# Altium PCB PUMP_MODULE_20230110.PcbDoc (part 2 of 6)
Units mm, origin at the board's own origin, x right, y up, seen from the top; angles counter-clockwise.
Board outline 260.15 x 142.01 mm, 4 copper layers (Top Layer, Mid-Layer 1, Mid-Layer 2, Bottom Layer); 422 components, 240 nets, 1746 pads, 416 vias.
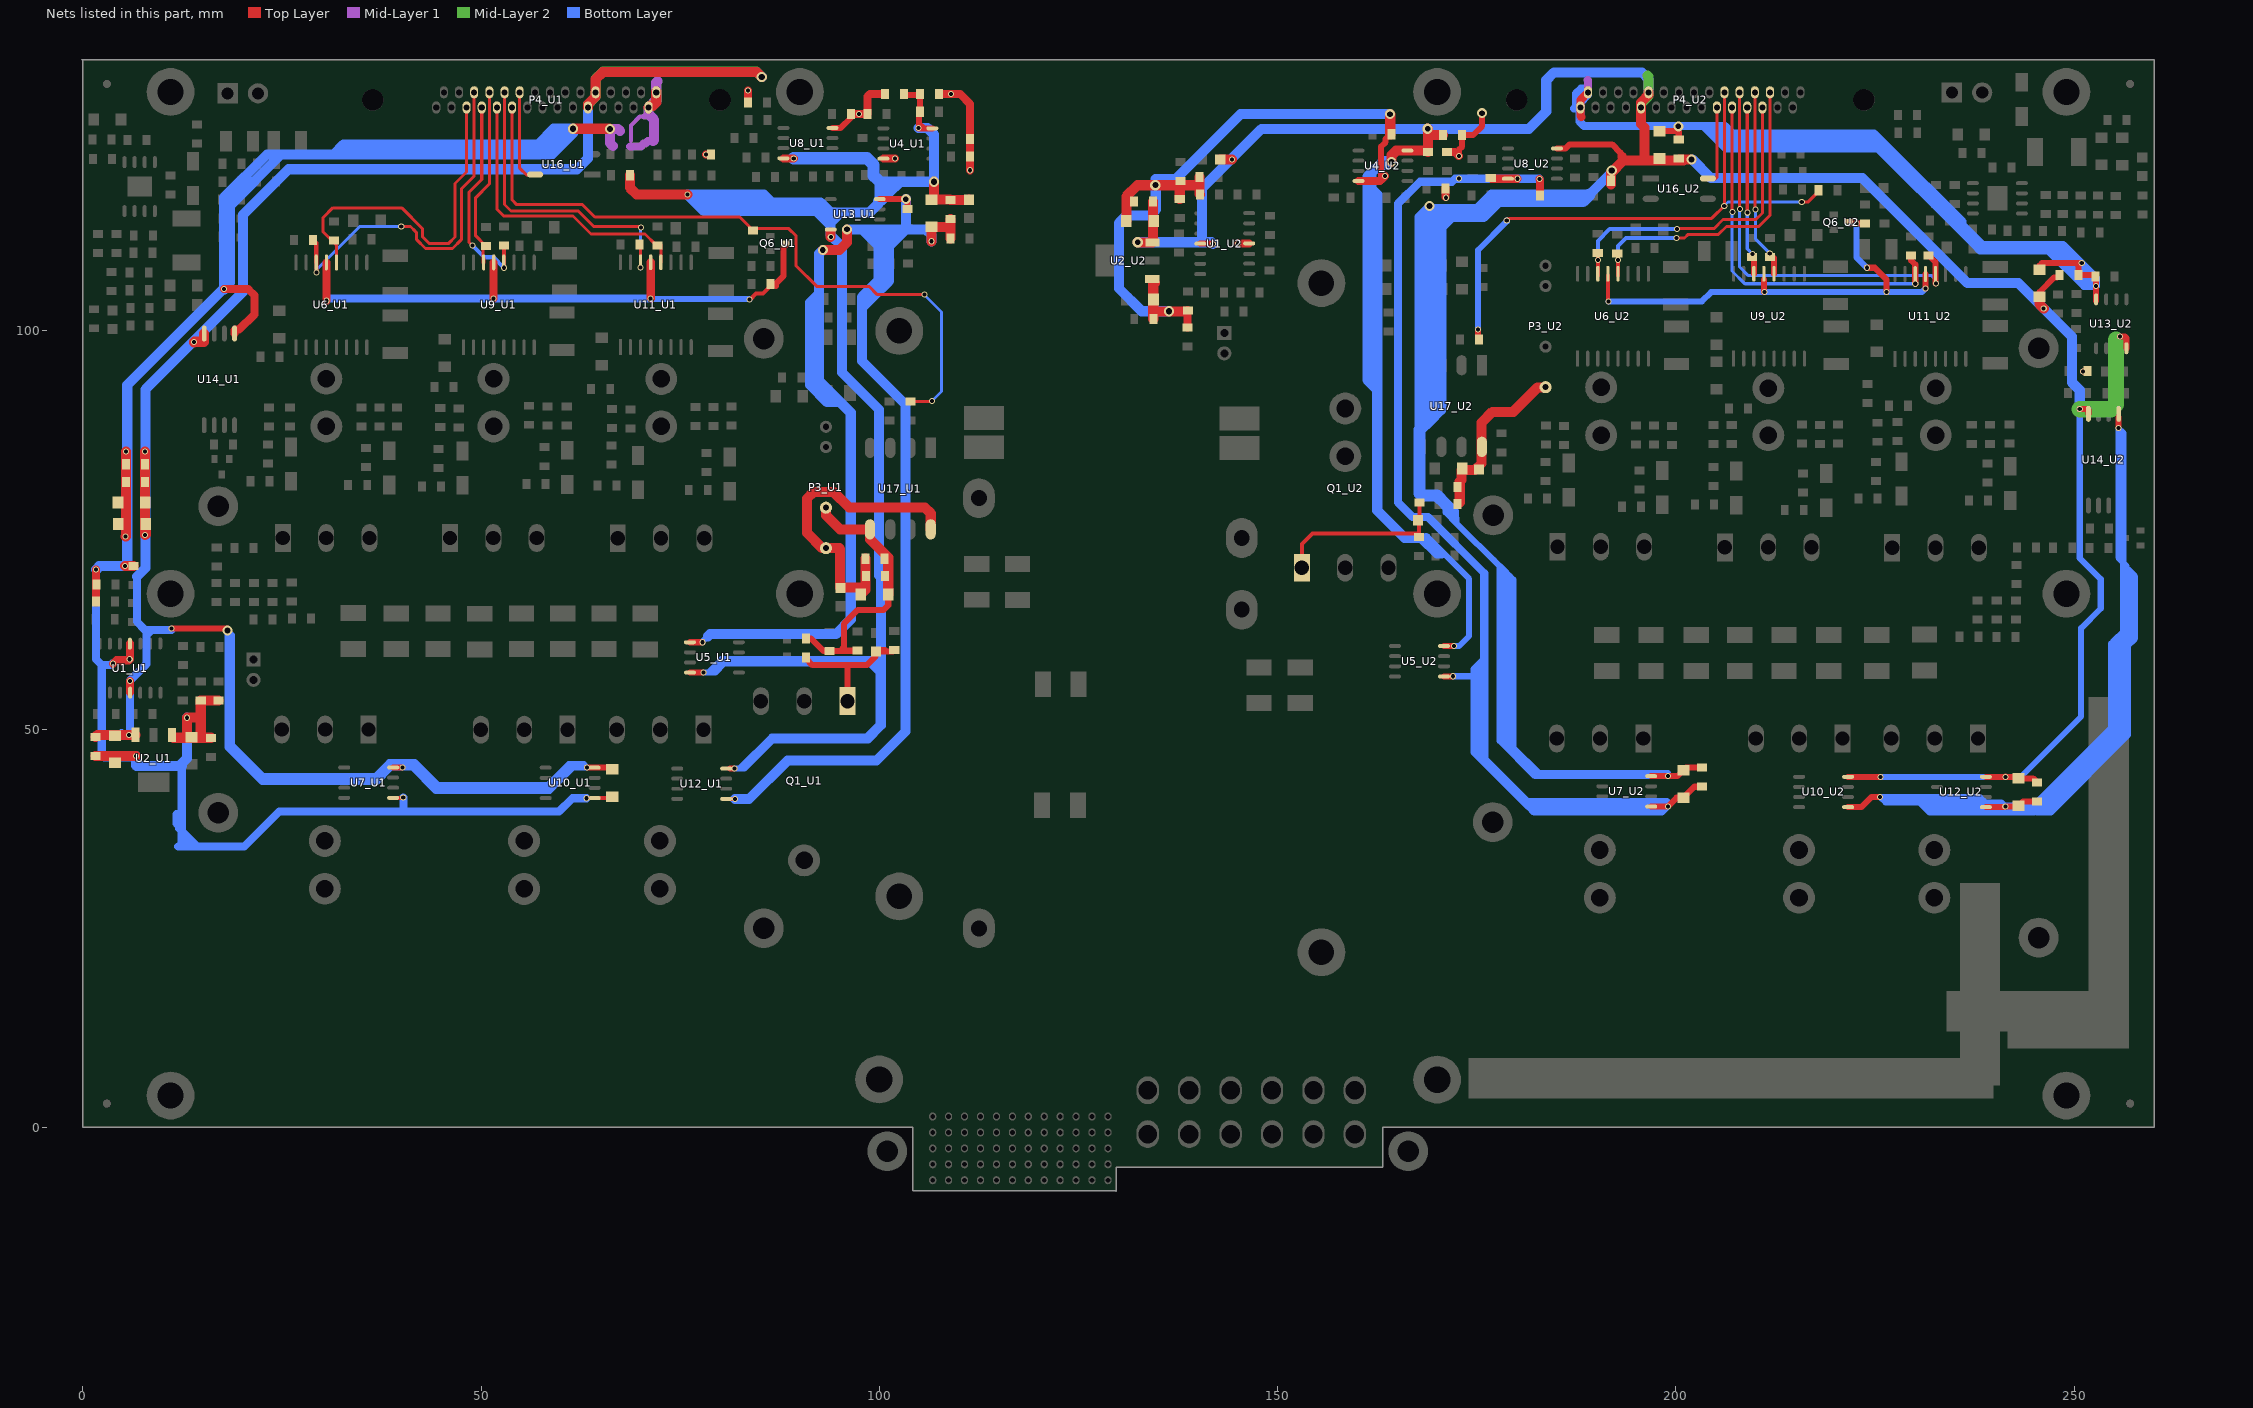
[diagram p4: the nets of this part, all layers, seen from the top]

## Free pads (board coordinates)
  rect 2.54x2.54 on Top Solder: 0(30.302,69.52) 0(51.587,69.596) 0(72.466,69.723) ""(161.417,9.855)
  rect 4.572x5.08 on Bottom Solder: 1(153.619,63.475) 1(190.221,54.534) 11(30.734,60.63) 11(30.759,55.448)
  rect 5.08x10.16 on Bottom Solder: 1(191.745,60.528) 1(195.301,64.186) 6(204.14,24.384) 6(204.14,33.35) 6(204.14,43.104) 7(243.713,85.573) 7(243.713,87.63)
  rect 5.08x8.89 on Bottom Solder: 1(224.714,58.268) 1(224.714,63.627) 1(234.315,58.42) 1(234.315,61.316) 1(236.957,63.957)
  rect 5.08x11.43 on Bottom Solder: 2(203.733,60.604) 2(204.14,53.467) 2(204.14,60.604) 2(213.411,60.274) 2(216.306,63.602)
  rect 5.08x3.81 on Bottom Solder: 3(232.664,54.077) 12(83.642,36.754) 12(91.999,40.869) 12(93.396,40.869) 12(98.273,40.869)
  rect 2.54x2.032 on Bottom Solder rot 135: 4(41.478,80.239) 4(41.656,80.797) 4(62.459,81.382) 4(201.016,79.832) 4(222.301,78.892) 4(224.231,68.224)
  rect 5.08x2.54 on Bottom Solder rot 45: 4(42.088,33.071)
  rect 5.08x3.81 on Bottom Solder rot 45: 4(191.11,57.455) 4(191.643,55.55) 4(192.329,66.091) 4(194.716,58.623) 4(214.071,66.091)
  rect 2.54x3.81 on Bottom Solder rot 135: 4(201.371,36.601) 4(216.56,54.254)
  rect 2.54x3.81 on Bottom Solder rot 45: 4(203.632,66.726) 4(213.106,54.153) 4(214.935,54.559) 4(224.765,54.534)
  rect 4.572x2.54 on Bottom Solder: 4(215.494,53.061) 11(75.082,68.275) 11(76.708,69.825)
  rect 2.54x3.81 on Bottom Solder: 4(216.51,56.007) 4(217.576,56.236)
  rect 2.54x2.54 on Bottom Solder rot 45: 4(222.453,85.7)
  rect 2.54x2.032 on Bottom Solder rot 45: 4(231.775,56.159) 4(234.264,64.059) 4(235.229,53.823) 4(235.509,68.047) 4(236.906,55.499) 4(237.871,59.334)
  rect 3.81x2.032 on Bottom Solder rot 45: 4(233.858,66.396)
  rect 3.81x2.032 on Bottom Solder: 4(237.592,68.656)
  rect 3.81x10.16 on Bottom Solder: 7(19.863,24.917) 7(70.891,61.341)
  rect 2.54x10.16 on Bottom Solder: 7(41.123,85.496) 7(41.123,94.386) 7(42.012,65.405) 7(42.012,75.54) 7(61.849,85.928) 7(61.849,94.437) 7(221.945,84.15) 7(221.945,89.789) 7(221.945,93.878) ""(163.728,8.204) ""(164.846,8.179)
  rect 2.032x8.89 on Bottom Solder: 7(41.758,53.213) 7(41.758,56.947) 7(42.266,53.061) 7(42.266,56.947) 7(44.247,53.162) 7(44.247,56.947) 7(44.247,65.202) 7(64.465,59.512) 7(64.745,64.719)
  rect 2.032x10.16 on Bottom Solder: 7(63.144,66.015) 7(63.144,76.175) 7(63.246,60.147) 7(202.184,65.913) 7(202.184,75.971) 7(223.19,72.771) 7(223.19,80.62) 7(226.238,57.379) 7(243.967,65.71)
  rect 3.302x10.16 on Bottom Solder: 7(200.914,85.014) 7(200.914,89.764) 7(200.914,93.751) 7(244.602,75.413)
  rect 3.302x7.62 on Bottom Solder: 7(236.855,59.461) 7(244.602,58.674)
  rect 4.572x10.16 on Bottom Solder: 10(30.251,58.014) 10(30.251,62.941) 10(34.595,65.888) 10(34.646,61.798) 10(52.299,61.468) 10(55.829,58.166) 10(55.829,65.837)
  rect 4.572x5.08 on Bottom Solder rot 135: 11(32.283,67.361) 11(33.198,56.667) 11(53.492,66.548)
  rect 4.572x5.08 on Bottom Solder rot 45: 11(53.442,56.515)
  rect 4.572x2.54 on Bottom Solder rot 45: 11(73.508,64.872) 11(76.479,67.843)
  rect 3x4.572 on Bottom Solder: 12(70.485,55.448)
  rect 4.572x4.572 on Bottom Solder rot 135: 12(72.796,66.243) 12(74.447,67.894)
  rect 3.81x5.08 on Bottom Solder: 12(83.007,33.35)
  rect 3.302x6.35 on Bottom Solder rot 135: 12(84.607,35.585) 12(87.274,38.252) 12(88.367,39.345)
  rect 4.572x7.112 on Bottom Solder: 12(91.897,21.971)
  rect 4.572x7.112 on Bottom Solder rot 135: 12(92.227,21.184) 12(93.802,26.391)
  rect 12.192x4.572 on Bottom Solder: 12(94.132,39.04)
  rect 4.572x7.112 on Bottom Solder rot 45: 12(95.225,37.211)
  rect 4.572x2 on Bottom Solder: 13(72.263,54.153)
  rect 4.572x2.54 on Bottom Solder rot 135: 14(71.933,55.855)
  round 1.016 smd: ""(3.025,3) ""(3.025,131) ""(257.025,3) ""(257.025,131)
  round 1.016 smd far side: ""(3.025,3) ""(3.025,131) ""(257.025,3) ""(257.025,131)
  round 6 hole 3.3: ""(11.025,4) ""(11.025,67) ""(11.025,130) ""(90.025,67) ""(90.025,130) ""(99.975,6.025) ""(170.025,6) ""(170.025,67) ""(170.025,130) ""(249.025,4) ""(249.025,67) ""(249.025,130)
  round 5 hole 2.7: ""(17,39.5) ""(17,78) ""(85.5,25) ""(85.5,99) ""(177.016,38.335) ""(177.041,76.83) ""(245.541,23.83) ""(245.541,97.83)
  rect 4.064x21.59 on Top Solder: ""(19.38,13.056) ""(19.38,23.495) ""(22.504,13.005) ""(22.555,31.115) ""(22.606,35.89) ""(37.008,26.111)
  rect 1.27x3.048 on Top Solder rot 135: ""(20.244,34.773) ""(188.798,68.174) ""(208.128,52.324) ""(209.956,68.174) ""(211.861,53.289) ""(228.981,53.238) ""(230.734,68.021) ""(234.848,55.118)
  rect 2.032x3.048 on Top Solder: ""(21.59,48.006) ""(21.59,50.495) ""(155.524,65.126)
  rect 2x3.81 on Top Solder: ""(22.25,49.53) ""(81.788,53.619)
  rect 2.032x3.5 on Top Solder rot 45: ""(22.682,47.193)
  rect 5.08x10.16 on Bottom Solder rot 45: ""(23.419,18.313) ""(47.295,19.101)
  rect 1.524x4.572 on Top Solder rot 135: ""(23.698,52.73)
  rect 3.048x2.032 on Top Solder: ""(26.314,53.873) ""(41.859,53.365) ""(47.549,53.289) ""(155.016,60.604) ""(185.395,52.172) ""(202.362,52.756) ""(203.378,51.714) ""(204.419,52.756) ""(205.969,51.714) ""(207.442,52.756)
  rect 2.032x3.81 on Top Solder rot 135: ""(27.33,55.524) ""(46.99,51.664) ""(48.666,53.34) ""(52.934,55.753) ""(68.58,54.889)
  rect 2.032x3.048 on Top Solder rot 135: ""(28.194,54.661) ""(49.936,69.063) ""(70.841,69.215) ""(100.838,49.581) ""(116.484,75.311) ""(149.301,61.824) ""(154.381,64.795) ""(186.411,53.34) ""(187.223,53.01)
  rect 3.048x3.81 on Top Solder: ""(29.642,41.224) ""(29.667,45.466) ""(54.788,41.046) ""(54.813,45.161) ""(71.476,41.123) ""(71.476,45.441) ""(138.43,10.82)
  rect 1.27x3.048 on Top Solder rot 45: ""(30.277,40.97) ""(33.858,38.684) ""(35.23,38.329) ""(55.575,40.792) ""(58.801,38.659) ""(60.147,38.532) ""(72.314,40.742) ""(75.971,38.583) ""(77.064,38.481) ""(192.43,68.25) ""(201.219,52.222) ""(208.102,53.264) ""(213.157,68.301) ""(225.171,53.264) ""(233.909,68.097)
  round 4 hole 2.2: ""(30.399,35.962) ""(30.585,88) ""(51.566,88) ""(55.393,35.962) ""(72.462,35.962) ""(72.623,88) ""(158.5,84.256) ""(190.456,34.83) ""(190.606,86.898) ""(211.612,86.898) ""(215.456,34.83) ""(232.456,34.83) ""(232.618,86.898)
  rect 10.16x3.81 on Top Solder: ""(30.759,55.601) ""(37.897,55.601) ""(47.219,55.601)
  rect 2.032x3.048 on Top Solder rot 45: ""(31.852,68.986) ""(53.213,69.063) ""(74.092,69.215) ""(79.451,63.805) ""(100.584,43.79)
  rect 3.048x1.016 on Top Solder: ""(32.385,39.827) ""(33.909,39.827) ""(57.683,39.649) ""(59.182,39.649) ""(73.863,39.726) ""(76.53,39.726)
  rect 3.048x5.08 on Top Solder rot 45: ""(36.195,37.592)
  rect 3.81x6.35 on Top Solder rot 45: ""(38.557,14.453)
  rect 5.08x10.16 on Bottom Solder rot 135: ""(39.294,19.406) ""(99.543,37.059) ""(106.451,44.348) ""(116.789,73.406)
  rect 2.032x3.81 on Top Solder rot 45: ""(40.513,53.467) ""(42.316,51.689) ""(64.262,54.889)
  rect 5.08x15.24 on Bottom Solder: ""(41.758,25.527) ""(95.377,17.882) ""(201.625,28.55)
  rect 50.8x10.16 on Bottom Solder: ""(43.358,15.342) ""(67.894,15.342)
  rect 5.08x25.4 on Bottom Solder: ""(44.298,23.139)
  rect 38.1x3.048 on Top Solder: ""(44.729,56.464) ""(53.975,56.464)
  rect 3.81x20.32 on Top Solder: ""(44.806,30.378) ""(44.806,47.295)
  rect 66.04x5.08 on Bottom Solder: ""(50.902,5.156) ""(207.137,5.969)
  rect 55.88x3.048 on Top Solder: ""(56.972,68.072)
  rect 65.04x5.08 on Bottom Solder: ""(57.81,5.232)
  rect 39.37x3.81 on Top Solder: ""(59.131,12.446) ""(85.192,18.898) ""(96.596,12.446) ""(109.626,12.446) ""(112.37,18.898)
  rect 3.048x4.064 on Top Solder rot 45: ""(61.011,37.694)
  rect 4.064x13.97 on Top Solder: ""(61.29,30.48)
  rect 3.81x8.89 on Top Solder rot 45: ""(63.779,21.717)
  rect 3.81x12 on Top Solder rot 45: ""(65.659,23.647)
  rect 3.048x2.286 on Top Solder: ""(66.421,53.975)
  rect 2.032x2.54 on Top Solder: ""(77.47,36.779)
  rect 2.54x3.81 on Top Solder: ""(77.724,36.5)
  rect 3.048x3.81 on Top Solder rot 45: ""(78.334,37.821)
  rect 11.43x3.048 on Top Solder: ""(79.019,65.202) ""(79.451,65.202) ""(84.099,38.024) ""(94.132,38.024) ""(102.057,38.024)
  rect 10.16x3.048 on Top Solder: ""(79.985,65.202)
  rect 8.89x3.048 on Top Solder: ""(81.636,36.093)
  rect 5.588x7.62 on Top Solder: ""(82.601,65.811)
  rect 3.048x3.81 on Top Solder rot 135: ""(86.36,37.008)
  rect 3.302x3.81 on Top Solder rot 45: ""(95.123,36.627) ""(118.542,30.15)
  rect 3.81x15.24 on Bottom Solder: ""(95.885,30.785) ""(96.012,27.737)
  rect 15.24x5.08 on Top Solder: ""(96.774,46.711) ""(169.469,50.749) ""(242.875,55.474) ""(249.377,55.499)
  rect 11.43x3.81 on Top Solder: ""(101.016,36.017)
  rect 7.62x12.7 on Top Solder rot 135: ""(107.772,52.553)
  rect 15.24x7.62 on Bottom Solder: ""(108.001,38.964) ""(143.281,57.633)
  rect 15.24x8.89 on Top Solder: ""(108.179,46.126) ""(109.982,46.126)
  rect 4.064x8.89 on Top Solder rot 45: ""(108.712,34.95) ""(126.314,73.228) ""(140.233,51.765) ""(152.806,44.12)
  rect 8.89x40.64 on Bottom Solder: ""(111.125,55.448)
  rect 8.89x20.32 on Top Solder: ""(113.182,53.289)
  rect 10.668x2.032 on Top Solder: ""(116.078,74.041) ""(124.816,74.092) ""(149.504,60.604)
  rect 19.05x4.572 on Top Solder: ""(119.939,32.639) ""(127.762,26.289) ""(127.762,28.372) ""(133.858,26.213) ""(133.858,30.505)
  rect 15.24x15.24 on Bottom Solder: ""(121.107,13.233)
  rect 2.032x3.81 on Bottom Solder rot 45: ""(124.257,5.385) ""(128.27,4.293) ""(129.337,3.226) ""(131.648,0.914) ""(230.327,11.836) ""(251.384,29.185) ""(256.413,19.888)
  rect 7.62x15.24 on Bottom Solder rot 135: ""(124.612,22.885) ""(139.802,43.688) ""(149.479,57.937)
  rect 2.032x3.81 on Bottom Solder: ""(125.705,5.029) ""(127.711,5.029)
  rect 22.86x8.89 on Top Solder: ""(127.61,78.537)
  rect 20.32x7.62 on Bottom Solder: ""(128.219,74.905) ""(128.245,78.715) ""(132.105,74.574) ""(132.105,78.715) ""(163.576,31.115)
  rect 2.54x10.16 on Bottom Solder rot 135: ""(129.769,11.024) ""(149.479,50.241) ""(155.702,62.814) ""(168.097,10.846) ""(241.884,9.042)
  rect 3.048x5 on Top Solder rot 45: ""(129.972,11.506)
  rect 2.54x1.27 on Top Solder: ""(131.877,9.296) ""(132.817,9.296) ""(190.602,68.377) ""(190.602,69.24) ""(209.956,52.375) ""(211.607,68.377) ""(211.633,69.418) ""(227.076,52.349) ""(232.613,69.037) ""(232.639,68.123)
  rect 1.27x2.54 on Top Solder rot 45: ""(132.359,10.363)
  rect 11.43x43.18 on Top Solder: ""(133.299,60.452)
  rect 15.24x50.8 on Bottom Solder: ""(133.756,36.017)
  rect 3.048x11.43 on Top Solder rot 45: ""(134.772,15.621)
  rect 4.572x22.86 on Top Solder rot 45: ""(135.458,25.248)
  rect 20.32x15.24 on Bottom Solder: ""(138.1,53.848)
  rect 3.032x5.048 on Top Solder rot 135: ""(139.573,77.267)
  rect 3.81x8.382 on Top Solder rot 45: ""(140.741,24.155)
  rect 3.81x6.35 on Top Solder: ""(141.478,23.114) ""(161.569,54.966)
  rect 20.32x8.89 on Top Solder: ""(141.681,45.999)
  rect 20.32x3.81 on Top Solder: ""(142.062,40.716) ""(162.128,40.716)
  rect 9.652x5.08 on Top Solder: ""(143.256,80.442)
  rect 3.048x10.16 on Top Solder: ""(143.535,13.818) ""(143.535,17.577)
  rect 15.32x7.62 on Bottom Solder: ""(147.93,54.508)
  rect 3.81x19.05 on Top Solder: ""(149.377,18.11)
  rect 3.81x8.382 on Top Solder rot 135: ""(151.841,28.88)
  rect 7.62x5.08 on Top Solder: ""(152.73,62.967)
  rect 2.54x5.08 on Top Solder: ""(154.889,11.151)
  rect 2.54x5.08 on Bottom Solder: ""(156.286,63.17)
  rect 7.62x15.32 on Bottom Solder: ""(157.607,58.369)
  rect 1x1 on Top Solder: ""(158.979,9.093) ""(159.69,9.093) ""(161.214,11.278) ""(167.081,9.119)
  rect 3.302x13.462 on Top Solder rot 135: ""(159.614,16.662) ""(161.874,18.898)
  rect 1.27x2 on Top Solder rot 135: ""(159.639,9.804) ""(160.35,9.754) ""(160.452,10.617) ""(167.843,9.779) ""(168.377,10.363)
  rect 2.54x10.16 on Bottom Solder rot 45: ""(160.833,26.391)
  rect 1.27x2.54 on Bottom Solder rot 135: ""(161.011,1.372)
  rect 2.032x2.032 on Top Solder rot 135: ""(161.087,64.033) ""(163.043,62.306)
  rect 2.54x1.27 on Bottom Solder: ""(161.112,-2.007)
  rect 1.27x2.54 on Bottom Solder: ""(161.112,0.432) ""(161.163,-0.33) ""(162.154,-1.372) ""(162.154,0.279) ""(162.154,1.473)
  rect 3.81x5.08 on Top Solder: ""(161.544,61.493)
  rect 3.81x3.81 on Top Solder rot 45: ""(162.382,51.791)
  rect 1.016x2.54 on Bottom Solder rot 45: ""(162.433,9.525) ""(240.386,19.634)
  rect 1.016x2.54 on Bottom Solder rot 135: ""(162.611,3.15)
  rect 5.08x3.81 on Top Solder: ""(162.916,64.008)
  rect 3.302x10.16 on Top Solder rot 135: ""(165.1,13.36) ""(225.908,14.783) ""(231.546,20.396) ""(234.671,23.52)
  rect 10.16x5.08 on Bottom Solder: ""(166.141,12.319)
  rect 12.7x20.32 on Bottom Solder: ""(167.437,22.504)
  rect 27.94x3.81 on Top Solder: ""(167.437,31.293)
  rect 2.032x3.81 on Bottom Solder rot 135: ""(171.704,11.811) ""(229.464,7.645) ""(251.765,19.634)
  rect 7.62x15.24 on Bottom Solder rot 45: ""(174.346,23.851)
  rect 5.08x7.62 on Top Solder rot 135: ""(176.301,53.645) ""(181.28,62.687) ""(181.61,58.953) ""(185.953,63.322)
  rect 3.81x7.62 on Top Solder: ""(178.105,59.284) ""(178.105,63.119)
  rect 35.56x3.81 on Top Solder: ""(181.762,23.901) ""(189.433,23.851)
  rect 4.572x6.35 on Top Solder rot 135: ""(182.016,33.274)
  rect 3.81x5.588 on Top Solder: ""(183.972,36.678) ""(183.972,36.678)
  rect 2.54x3.048 on Top Solder rot 135: ""(184.048,39.649)
  rect 3.81x5.588 on Top Solder rot 135: ""(185.344,38.456) ""(205.969,38.557)
  rect 38.1x3.81 on Top Solder: ""(186.588,16.205)
  rect 5.588x3.81 on Top Solder: ""(186.588,40.081)
  rect 25.4x5.08 smd: ""(186.665,6.172) ""(210.414,6.172) ""(227.203,6.172)
  rect 2.54x3.048 on Top Solder: ""(188.112,44.018)
  rect 33.02x3.81 on Top Solder: ""(192.71,66.015) ""(218.999,66.04)
  rect 50.1x1.524 on Top Solder: ""(193.675,10.77) ""(198.222,10.77)
  rect 4.572x10.16 on Top Solder rot 135: ""(201.524,27.203)
  rect 4.572x7.16 on Top Solder rot 135: ""(203.022,26.213)
  rect 33.02x2.54 on Top Solder: ""(203.276,53.873) ""(210.49,53.873)
  rect 4.572x10.16 on Top Solder: ""(204.927,30.709) ""(204.927,33.071)
  rect 66.04x10.16 on Bottom Solder: ""(205.257,16.789)
  rect 3.81x7.62 on Top Solder rot 135: ""(206.781,37.135)
  rect 12.7x3.81 on Top Solder: ""(208.686,16.205)
  rect 7.62x3.81 on Top Solder: ""(210.312,39.954)
  rect 3.556x2.54 on Top Solder: ""(212.293,43.663) ""(229.667,43.663) ""(229.743,39.98) ""(232.461,19.279)
  rect 4.572x12.7 on Top Solder rot 135: ""(217.907,20.599) ""(222.58,25.273)
  rect 2x5 on Top Solder rot 135: ""(222.783,12.548)
  rect 5.08x8.89 on Top Solder: ""(226.162,32.106)
  rect 3.556x7.112 on Top Solder rot 135: ""(227.381,37.44) ""(233.68,9.347) ""(237.617,24.13) ""(241.452,29.159) ""(242.799,9.246) ""(250.876,16.231) ""(251.308,35.128)
  rect 10.16x15.24 on Bottom Solder: ""(235.102,14.199)
  rect 3.556x7.112 on Top Solder: ""(235.661,19.38)
  rect 5.08x25.4 smd: ""(238.176,17.958) ""(254.356,24.765) ""(254.356,41.326)
  rect 3.556x5 on Top Solder rot 135: ""(238.531,31.217)
  rect 5.08x30.48 on Top Solder: ""(239.243,18.771)
  rect 3.556x7.112 on Top Solder rot 45: ""(240.335,18.491) ""(250.977,29.362) ""(251.231,53.035)
  rect 30.48x2.54 on Top Solder: ""(241.757,53.873)
  rect 15.24x10.16 on Bottom Solder: ""(242.468,14.224) ""(251.054,14.275)
  rect 20.32x5.08 smd: ""(244.145,14.58)
  rect 20.32x5.08 on Top Solder: ""(246.863,32.106)
  rect 15.24x5.08 smd: ""(249.276,12.446)
  rect 15.24x5.08 on Bottom Solder: ""(249.276,32.106)
  rect 5.08x20.32 on Bottom Solder: ""(254.33,24.435)

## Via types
v1: diameter 0.762, hole 0.508, Top Layer to Bottom Layer, 208 vias
v2: diameter 2.032, hole 1.27, Top Layer to Bottom Layer, 78 vias
v3: diameter 1.27, hole 0.762, Top Layer to Bottom Layer, 61 vias
v4: diameter 1.524, hole 1.016, Top Layer to Bottom Layer, 53 vias
v5: diameter 1.27, hole 0.711, Top Layer to Bottom Layer, 16 vias

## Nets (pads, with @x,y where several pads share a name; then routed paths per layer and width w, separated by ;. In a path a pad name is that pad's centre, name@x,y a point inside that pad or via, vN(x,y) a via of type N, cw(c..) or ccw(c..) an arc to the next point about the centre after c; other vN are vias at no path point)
1PWM1_U1: P4_U1.3 R31_U1.1 U6_U1.12 | length 42.6
  Top Layer w0.381: U6_U1.12@31.877,109.017 31.877,110.719 30.175,112.42 30.175,114.224 31.394,115.443 40.03,115.443 42.621,112.852 42.621,111.836 43.459,110.998 45.949,110.998 46.736,111.785 46.736,118.491 48.184,119.939 P4_U1.3@48.184,128.047
1PWM1_U2: P4_U2.3 R31_U2.1 U6_U2.12 | length 40.4
  Top Layer w0.381: v1(200.076,111.658) 201.092,111.658 201.549,112.116 205.359,112.116 206.35,113.106 210.416,113.106 211.813,114.503 P4_U2.3@211.813,129.952
  Top Layer w0.508: U6_U2.12@192.735,106.967 U6_U2.12@192.735,107.17 v1(192.735,108.915) R31_U2.1@192.735,109.525
  Bottom Layer w0.508: v1(192.735,108.915) 192.735,110.642 193.751,111.658 v1(200.076,111.658)
1PWM2_U1: P4_U1.18 R33_U1.1 U6_U1.14 | length 46.8
  Top Layer w0.381: v1(39.98,113.106) 41.142,113.106 41.745,112.503 41.745,112.484 41.91,112.319 41.91,111.455 43.028,110.338 46.406,110.338 47.523,111.455 47.523,117.818 49.137,119.431 P4_U1.18@49.136,129.952
  Top Layer w0.508: R33_U1.1@28.931,111.404 29.312,111.023 U6_U1.14@29.312,108.592 ; v1@29.337,107.34 U6_U1.14@29.337,109.118
  Bottom Layer w0.381: v1(29.362,107.34) 29.362,107.696 34.773,113.106 v1(39.98,113.106)
1PWM2_U2: P4_U2.18 R33_U2.1 U6_U2.14 | length 40.6
  Top Layer w0.381: v1(200.152,112.776) 200.203,112.827 204.775,112.827 205.918,113.97 210.033,113.97 210.861,114.798 P4_U2.18@210.861,128.047
  Top Layer w0.508: U6_U2.14@190.195,106.967 U6_U2.14@190.195,107.17 v1(190.195,108.89) R33_U2.1@190.195,109.804
  Bottom Layer w0.508: v1(190.195,108.89) 190.195,111.277 191.694,112.776 v1(200.152,112.776)
1PWM3_U1: P4_U1.4 R48_U1.1 U9_U1.12 | length 26.7
  Top Layer w0.381: v1(48.92,110.693) 48.514,111.1 48.514,117.424 50.089,118.999 ; 50.089,119.675 50.089,118.999 ; P4_U1.4@50.089,128.047 50.089,118.999
  Top Layer w0.508: v1(52.857,107.925) R48_U1.1@52.857,110.642
  Bottom Layer w0.508: v1(48.92,110.693) 50.368,109.245 51.537,109.245 v1(52.857,107.925)
1PWM3_U2: P4_U2.4 R48_U2.1 U9_U2.12 | length 23
  Top Layer w0.381: v1@209.908,115.24 209.908,127.398 ; 209.908,127.398 209.908,128.696 P4_U2.4@209.908,129.952
  Top Layer w0.762: U9_U2.12@212.319,107.17 U9_U2.12@212.319,107.442 ; U9_U2.12@212.319,107.373 R48_U2.1@212.319,109.118
  Bottom Layer w0.381: v1(209.982,115.24) 210.007,115.214 210.007,111.506 v1(211.785,109.728)
1PWM4_U1: P4_U1.19 R50_U1.1 U9_U1.14 | length 24.1
  Top Layer w0.381: U9_U1.14@50.267,109.169 50.267,110.287 R50_U1.1@50.622,110.642 49.276,111.989 49.276,116.662 51.042,118.428 ; 51.042,119.736 51.042,118.428 ; P4_U1.19@51.041,129.952 51.042,118.428
  Top Layer w0.508: U9_U1.14@50.317,108.592 U9_U1.14@50.317,109.118
1PWM4_U2: P4_U2.19 R50_U2.1 U9_U2.14 | length 20.4
  Top Layer w0.381: v1@208.956,114.833 P4_U2.19@208.956,128.047
  Top Layer w0.762: U9_U2.14@209.779,107.17 R50_U2.1@209.779,108.941
  Bottom Layer w0.381: v1@208.956,114.833 208.956,110.297 v1(209.601,109.652)
  other v1: 208.966,114.833
1PWM5_U1: P4_U1.5 R63_U1.1 U11_U1.12 | length 37.4
  Top Layer w0.381: P4_U1.5@51.994,128.047 51.994,115.265 52.832,114.427 61.544,114.427 63.805,112.166 70.587,112.166 71.94,110.813 72.568,110.813 U11_U1.12@72.568,108.618
1PWM5_U2: P4_U2.5 R63_U2.1 U11_U2.12 | length 51.6
  Top Layer w0.381: v1@208.003,115.316 P4_U2.5@208.003,129.952
  Top Layer w0.762: R63_U2.1@231.724,109.499 232.588,108.636 U11_U2.12@232.588,107.145 v1@232.588,105.969
  Bottom Layer w0.381: v1@208.003,115.316 208.003,108.023 209.093,106.934 232.131,106.934 232.639,106.426 v1(232.639,105.969)
  other v1: 208.026,115.316
1PWM6_U1: P4_U1.20 R65_U1.1 U11_U1.14 | length 40.7
  Top Layer w0.381: P4_U1.20@52.946,129.952 52.947,115.862 53.746,115.062 62.205,115.062 64.186,113.081 69.875,113.081 v1@70.053,112.903 ; v1(70.028,107.95) R65_U1.1@70.028,111.118
  Bottom Layer w0.381: v1@70.028,107.798 v1@70.028,112.903
  other v1: 70.053,113.005
1PWM6_U2: P4_U2.20 R65_U2.1 U11_U2.14 | length 48.1
  Top Layer w0.381: v1@207.051,114.91 P4_U2.20@207.051,128.047
  Top Layer w0.762: R65_U2.1@229.514,109.55 229.514,108.864 230.048,108.331 U11_U2.14@230.048,107.391 ; v1(230.048,105.918) U11_U2.14@230.048,107.145 U11_U2.14@230.048,107.391 ; U11_U2.14@230.073,107.417 U11_U2.14@230.048,107.391
  Bottom Layer w0.381: v1@207.051,114.91 207.051,107.528 208.661,105.918 v1(230.048,105.918)
  other v1: 207.086,114.91
+5VA_U1: C1_U1.1 C4_U1.1 C55_U1.1 C56_U1.1 C57_U1.1 C58_U1.2 C59_U1.2 C60_U1.2 C62_U1.1 C63_U1.1 C65_U1.1 D19_U1.1 P4_U1.11 P4_U1.26 R13_U1.2 R85_U1.1 U1_U1.4 U2_U1.3 U4_U1.8 U5_U1.8 U7_U1.8 U8_U1.8 U10_U1.8 U12_U1.8 U13_U1.8 U14_U1.8 | length 640.1
  Top Layer w0.762: v1(11.151,62.662) v3@18.186,62.662 ; U7_U1.8@38.964,45.187 v1(40.157,45.187) ; v1(63.297,45.161) U10_U1.8@64.262,45.161 66.269,45.161 C55_U1.1@66.472,44.958 ; U5_U1.8@76.225,57.099 v1(77.927,57.099) ; U12_U1.8@81.28,45.085 v1(81.839,45.085) ; C60_U1.2@103.099,129.616 104.978,129.616 C58_U1.2@105.08,129.718 105.105,129.692 R13_U1.2@105.105,127.508 ; R13_U1.2@104.953,127.533 104.953,126.035 ; U4_U1.8@106.655,125.425 105.562,125.425 ; 104.953,126.035 105.562,125.425 ; 104.953,126.035 104.953,125.501 v1(104.902,125.451) 104.927,125.425 105.562,125.425
  Top Layer w1.016: v1(5.918,56.032) 5.944,56.007 U1_U1.4@5.944,54.585 ; U8_U1.8@87.96,121.666 v1(89.256,121.666)
  Top Layer w1.27: C4_U1.1@1.575,48.997 1.829,49.251 U2_U1.3@6.629,49.251 ; v1(7.798,84.836) 7.823,84.811 C63_U1.1@7.823,81.026 v1(7.823,74.371) 7.899,74.447 C56_U1.1@7.899,75.768 ; v1(13.97,98.577) 14.021,98.628 15.189,98.628 15.24,98.679 U14_U1.8@15.24,99.67 ; P4_U1.11@63.424,128.047 63.424,128.448 64.376,129.4 P4_U1.26@64.376,129.952 64.376,131.584 65.278,132.486 84.633,132.486 v3(85.242,131.877) ; R85_U1.1@68.682,119.532 68.682,117.983 69.545,117.119 v1(75.895,117.119) ; v1@93.853,111.785 93.853,112.293 ; 93.853,112.344 93.853,112.293 ; 93.878,112.319 93.853,112.293 ; v3(106.883,118.72) 106.883,116.815 C65_U1.1@106.553,116.484 108.864,116.484 C59_U1.2@108.915,116.434 111.252,116.434 D19_U1.1@111.277,116.459
  Mid-Layer 2 w1.27: P4_U1.11@63.424,128.047 63.424,128.397 64.376,129.349 P4_U1.26@64.376,129.952 64.414,129.99 64.414,131.674 65.303,132.563 84.557,132.563 v3(85.242,131.877)
  Bottom Layer w0.762: v1(77.927,57.099) 78.511,57.099 ; v1(81.839,45.085) 82.474,45.085 ; 78.511,57.099 79.4,57.099 80.543,58.242 98.704,58.242 ; 78.511,57.099 80.188,58.776 99.949,58.776 ; 82.474,45.085 83.083,45.085 86.563,48.565 98.628,48.565 100.457,50.394 100.457,58.42 ; 82.474,45.085 86.462,49.073 98.374,49.073 99.898,50.597 99.898,57.048 ; 98.704,58.242 99.949,58.242 ; 98.704,58.242 99.898,57.048 ; 99.898,57.048 99.898,57.506 ; 99.898,57.506 99.898,58.191 99.949,58.242 ; 99.898,57.506 99.949,57.556 99.949,58.242 ; 99.949,58.242 100.279,58.242 100.457,58.42 ; 99.949,58.242 99.949,58.776 ; 99.949,58.776 99.949,69.291 100.025,69.367 100.457,69.367 100.457,58.42 ; 99.949,58.776 100.101,58.776 100.457,58.42 ; 18.161,47.701 22.504,43.358 36.906,43.358 38.735,45.187 v1(40.157,45.187) 41.351,45.187 44.272,42.266 58.623,42.266 61.519,45.161 v1(63.297,45.161) 62.89,45.568 62.89,45.618 61.316,45.618 61.29,45.593 61.011,45.593 58.395,42.977 44.602,42.977 41.732,45.847 38.456,45.847 36.728,44.12 22.657,44.12 18.72,48.057 18.72,61.824 v3(18.161,62.382) 18.161,47.701
  Bottom Layer w1.016: 4.851,49.505 5.08,49.276 v1(5.817,49.276) ; v1@5.918,49.505 v1(5.918,56.032) 5.918,56.109 8.001,58.191 8.001,61.798 ; 6.807,69.164 6.807,66.811 6.782,66.786 6.782,63.5 7.823,62.459 ; v1@11.125,62.459 8.687,62.459 ; 7.823,62.459 8.001,62.281 8.001,61.798 ; 7.823,62.459 8.661,62.459 ; 8.001,61.798 8.661,62.459 ; 8.661,62.459 8.674,62.471 8.687,62.459 ; 8.661,62.459 8.687,62.459
  Bottom Layer w1.27: 6.807,69.164 7.874,70.231 7.874,92.659 20.117,104.902 20.117,114.579 25.832,120.294 62.052,120.294 63.424,121.666 P4_U1.11@63.424,128.047 ; 99.949,69.291 99.949,90.119 95.301,94.767 95.301,110.592 93.853,112.039 93.853,113.284 ; 99.974,116.281 99.974,116.078 98.781,114.884 95.199,114.884 ; 100.178,116.281 101.155,117.259 ; 100.178,118.593 100.305,118.72 101.067,118.72 ; v1(104.902,125.451) 106.07,125.451 106.883,124.638 v3(106.883,118.72) 102.616,118.72 ; 76.911,116.103 77.978,115.037 87.579,115.037 ; 76.911,116.103 v1(75.895,117.119) 85.496,117.119 86.512,116.103 ; 76.911,116.103 86.512,116.103 ; 86.512,116.103 92.634,116.103 93.853,114.884 ; 86.512,116.103 87.579,115.037 ; 87.579,115.037 92.1,115.037 93.853,113.284 ; 93.853,113.284 93.853,113.538 ; 93.853,113.538 93.853,114.884 ; 93.853,113.538 95.199,114.884 ; 93.853,114.884 95.199,114.884 ; 101.067,118.72 101.155,118.631 101.155,117.259 ; 101.067,118.72 102.616,118.72 ; 101.155,117.259 102.616,118.72
  Bottom Layer w1.524: v1(89.256,121.666) 98.45,121.666 99.289,120.828 99.289,119.482 100.178,118.593 100.178,116.484 99.974,116.281
  other v1: 93.904,111.785
+5VA_U2: C1_U2.1 C4_U2.1 C55_U2.1 C56_U2.1 C57_U2.1 C58_U2.2 C59_U2.2 C60_U2.2 C62_U2.1 C63_U2.1 C65_U2.1 D19_U2.1 P4_U2.11 P4_U2.26 R13_U2.2 R85_U2.1 U1_U2.4 U2_U2.3 U4_U2.8 U5_U2.8 U7_U2.8 U8_U2.8 U10_U2.8 U12_U2.8 U13_U2.8 U14_U2.8 | length 713.5
  Top Layer w0.762: U1_U2.4@140.284,110.947 141.859,110.947 v1(141.884,110.922) ; U5_U2.8@170.891,60.427 v1(172.136,60.427) ; U8_U2.8@185.064,122.911 186.157,122.911 186.665,123.419 191.999,123.419 193.04,122.377 ; U7_U2.8@196.901,44.094 v1(198.984,44.094) 200.203,44.094 C55_U2.1@200.939,44.831 201.27,45.161 C58_U2.2@203.276,45.161 ; U10_U2.8@221.615,44.018 223.799,44.018 223.825,43.993 v1(225.679,43.993) ; U12_U2.8@238.912,44.018 241.325,44.018 v1@241.376,44.069 ; v1(241.376,44.018) 242.824,44.018 C56_U2.1@243.027,43.815 244.856,43.815 C60_U2.2@245.339,43.332 ; C57_U2.1@245.643,104.267 245.643,104.866 247.483,106.705 247.828,106.705 C59_U2.2@248.133,107.01 ; v1(250.698,90.17) 250.723,90.195 251.739,90.195 251.79,90.145 U14_U2.8@251.79,89.586 ; v1@255.753,99.289 256.388,99.289 256.565,99.111 U13_U2.8@256.565,97.815 ; 193.04,122.377 193.421,121.996 193.421,121.412 193.04,121.793 193.04,122.377
  Top Layer w1.27: v5(132.436,111.125) 132.436,111.074 132.461,111.1 U2_U2.3@134.29,111.1 134.366,111.176 C4_U2.1@134.366,116.23 ; D19_U2.1@142.799,121.514 v1(144.272,121.514) ; v3(164.313,121.183) 164.313,122.047 164.897,122.631 U4_U2.8@166.294,122.631 168.681,122.631 R13_U2.2@168.859,122.453 168.859,124.638 ; v5(168.834,125.374) 168.859,125.349 168.859,124.638 ; C63_U2.1@170.764,124.587 168.91,124.587 168.859,124.638 ; R85_U2.1@191.872,118.415 191.872,119.863 193.421,121.412 196.24,121.412 ; P4_U2.11@196.573,129.952 196.573,129.627 195.621,128.675 P4_U2.26@195.621,128.047 195.621,125.968 196.063,125.527 196.063,121.59 196.24,121.412 ; C62_U2.1@200.457,121.539 201.066,121.539 ; v3(201.981,121.539) 201.066,121.539 ; C57_U2.1@245.643,104.267 245.643,103.353 v1(246.177,102.819) ; 196.24,121.412 200.939,121.412 201.066,121.539
  Mid-Layer 2 w1.27: 195.631,126.416 195.621,126.426 P4_U2.26@195.621,128.047 195.621,128.514 196.573,129.466 P4_U2.11@196.573,129.952 196.573,131.9 196.444,132.029
  Mid-Layer 2 w2.032: v1(250.698,90.17) 254.66,90.17 255.245,90.754 255.245,98.857 255.27,98.882
  Bottom Layer w0.762: 162.179,119.913 162.865,120.599 ; 168.021,74.016 168.046,74.016 168.628,74.016 168.897,74.016 174.041,68.872 174.041,61.697 172.771,60.427 v1(172.136,60.427) ; 171.094,78.257 171.094,78.232 171.094,77.216 172.441,75.87 ; 172.034,76.911 172.441,76.505 172.441,75.87 ; 177.14,71.222 178.435,69.926 ; v1(225.679,43.993) 243.281,43.993 250.876,51.587 250.876,62.687 253.34,65.151 253.34,68.834 250.698,71.476 v1(250.698,90.17) ; 162.865,120.599 163.449,121.183 ; 162.865,120.599 163.728,120.599 v3(164.313,121.183) ; 163.449,121.183 163.093,121.183 163.5,121.59 163.906,121.59 v3(164.313,121.183) ; 163.449,121.183 v3(164.313,121.183) ; 172.441,75.87 177.876,70.434 177.876,48.514 182.296,44.094 v1(198.984,44.094) 198.984,44.45 199.034,44.501 182.778,44.501 179.603,47.676 ; 178.435,69.926 179.146,69.215 ; 178.435,69.926 178.435,48.844 179.146,48.133 ; 179.146,48.133 179.603,47.676 ; 179.146,48.133 179.146,69.215 ; 179.146,69.215 179.603,68.758 179.603,47.676
  Bottom Layer w1.27: v5(132.436,111.125) 140.513,111.125 ; v1(141.884,110.922) 141.681,111.125 140.513,111.125 ; 163.093,121.183 161.773,119.863 ; 167.818,87.579 167.818,114.275 168.834,115.291 170.536,115.291 ; 168.021,74.016 165.938,74.016 162.509,77.445 162.509,92.583 ; 168.046,74.016 170.004,72.058 170.585,72.058 ; 168.628,74.016 168.763,73.881 ; 170.358,115.011 170.637,115.291 175.031,115.291 176.86,117.119 189.154,117.119 v3@192.049,120.015 ; P4_U2.11@196.573,129.952 196.573,131.595 195.732,132.436 184.683,132.436 183.718,131.47 183.718,127.533 181.534,125.349 147.955,125.349 140.487,117.881 140.487,111.15 140.513,111.125 ; v3(201.981,121.539) 202.057,121.539 204.419,119.177 223.418,119.177 236.601,105.994 243.002,105.994 v1(246.177,102.819) 249.707,99.289 249.707,93.548 250.698,92.558 v1(250.698,90.17) ; 161.773,119.863 161.265,119.355 161.265,93.828 162.509,92.583 ; 161.773,119.863 161.773,117.856 162.509,117.119 162.509,92.583
  Bottom Layer w1.524: 170.358,115.011 170.256,115.011 169.062,113.817 169.062,88.824 ; 172.034,76.911 172.034,77.292 171.094,78.232 170.002,79.324 168.097,79.324 167.818,79.604 167.818,87.579 169.062,88.824 ; 189.154,117.119 188.341,116.307 177.698,116.307 175.819,114.427 171.78,114.427 170.409,113.055 170.409,90.17 169.062,88.824
  other v1: 255.753,99.314
  other v3: 169.088,115.697 191.948,120.117
+15V_HVISO_U1: C38_U1.1 C39_U1.1 C40_U1.1 D8_U1.1 P3_U1.4 U17_U1.8 | length 41.4
  Top Layer w1.27: C40_U1.1@98.273,71.399 98.273,67.488 C38_U1.1@97.688,66.904 97.688,67.767 95.072,67.767 95.072,72.619 94.971,72.72 P3_U1.4@93.294,72.72 92.837,72.72 90.907,74.651 90.907,78.969 91.694,79.756 94.285,79.756 96.215,77.826 105.715,77.826 106.451,77.089 U17_U1.8@106.451,75.082
+15V_HVISO_U2: C38_U2.1 C39_U2.1 C40_U2.1 D8_U2.1 P3_U2.4 U17_U2.8 | length 22
  Top Layer w1.27: C39_U2.1@172.872,78.461 172.872,81.077 173.076,81.28 173.076,82.55 174.777,82.55 175.59,83.363 175.59,88.468 176.962,89.84 179.578,89.84 182.651,92.913 P3_U2.4@183.591,92.913
AGND_U1: C1_U1.2 C2_U1.2 C3_U1.2 C4_U1.2 C12_U1.2 C14_U1.2 C33_U1.2 C46_U1.2 C53_U1.2 C55_U1.2 C56_U1.2 C57_U1.2 C58_U1.1 C59_U1.1 C60_U1.1 C62_U1.2 C63_U1.2 C64_U1.2 C65_U1.2 P4_U1.15 P4_U1.30 R9_U1.1 R10_U1.1 R11_U1.2 R12_U1.2 R14_U1.1 R71_U1.1 R72_U1.2 U1_U1.11 U2_U1.1 U4_U1.4 U5_U1.5 U7_U1.5 U8_U1.4 U10_U1.5 U12_U1.5 U13_U1.4 U14_U1.5 | length 622.8
  Top Layer w0.508: U7_U1.5@38.964,41.377 40.208,41.377 v1(40.234,41.402) ; v1(63.246,41.326) 63.271,41.351 U10_U1.5@64.262,41.351 66.294,41.351 C55_U1.2@66.472,41.529 ; U12_U1.5@80.874,41.25 v1@81.966,41.25
  Top Layer w0.762: U5_U1.5@76.225,60.909 v1(77.775,60.909) ; U8_U1.4@94.107,125.476 95.148,125.476 96.444,126.771 C46_U1.2@96.444,127.203 ; U13_U1.4@100.051,116.535 103.226,116.535 103.53,116.23 C64_U1.2@103.53,115.291
  Top Layer w1.016: R9_U1.1@1.676,65.913 R9_U1.1@1.676,66.04 v1(1.676,70.028) ; v1(3.81,58.217) 4.242,58.649 5.766,58.649 v1(5.893,58.776) 5.918,58.801 U1_U1.11@5.918,60.731 ; v1(17.755,105.232) 20.777,105.232 21.539,104.47 21.539,102.057 19.634,100.152 19.126,100.152 19.05,100.076 U14_U1.5@19.05,99.67 ; v1(78.232,122.123) R72_U1.2@78.765,122.123 ; C53_U1.2@83.515,128.651 v1(83.515,130.2) ; C46_U1.2@96.444,127.203 v1(97.472,127.203) C33_U1.2@98.501,127.203 98.501,129.413 98.806,129.718 C60_U1.1@100.711,129.718 ; U4_U1.4@100.508,121.615 101.93,121.615 v1(101.956,121.641) ; C58_U1.1@107.467,129.718 v1(109.017,129.718) 110.16,129.718 111.379,128.499 R14_U1.1@111.379,124.079 C14_U1.2@111.379,121.895 v1(111.379,120.167)
  Top Layer w1.27: C4_U1.2@1.575,46.609 v1(6.706,46.609) ; v1(5.309,70.46) 5.334,70.485 R12_U1.2@6.35,70.485 ; v1(5.359,74.168) 5.41,74.219 C62_U1.2@5.41,83.261 v1(5.41,84.836) ; U2_U1.1@11.379,48.92 C2_U1.2@13.716,48.92 ; v1(13.081,51.435) v1@13.106,51.41 ; C2_U1.2@13.106,49.225 v1@13.106,51.41 ; C2_U1.2@13.741,48.946 C2_U1.2@13.716,48.92 ; 14.808,48.946 14.808,51.486 ; C3_U1.2@16.104,48.92 C2_U1.2@13.716,48.92 ; R11_U1.2@17.043,53.619 R10_U1.1@14.808,53.619 14.808,51.486 ; v3(61.544,125.374) 66.142,125.374 v3@66.192,125.324 ; P4_U1.15@71.044,128.047 71.267,128.27 71.577,128.27 71.996,128.689 P4_U1.30@71.996,129.952 ; v5(92.913,110.16) 95.009,110.16 95.948,111.1 v5(95.948,112.751) ; v1(106.553,111.252) C65_U1.2@106.553,113.055 108.585,113.055 108.915,113.386 ; R71_U1.1@108.915,111.582 108.915,113.386 ; C59_U1.1@108.915,114.046 108.915,113.386 ; v1@13.106,51.41 13.183,51.486 14.808,51.486
  Mid-Layer 1 w0.508: 68.809,123.901 68.809,125.806 69.922,126.92 70.453,126.92
  Mid-Layer 1 w0.762: 70.453,126.92 70.786,126.92 71.044,127.178
  Mid-Layer 1 w1.016: 68.732,123.165 70.062,123.165 70.418,123.52 70.662,123.52 70.967,123.825 71.577,123.825
  Mid-Layer 1 w1.27: 66.573,123.19 66.192,123.571 v3(66.192,125.349) 67.208,125.349 67.462,125.095 ; 71.577,123.825 71.73,123.977 71.73,126.492 71.044,127.178 P4_U1.15@71.044,128.047 71.996,128.999 P4_U1.30@71.996,129.952 71.996,131.178 72.161,131.343
  Bottom Layer w0.508: v1@63.17,41.402 v1(63.246,41.326)
  Bottom Layer w0.762: v1(77.775,60.909) 77.775,60.96 78.486,61.671
  Bottom Layer w1.016: v1(1.676,70.028) 1.676,58.776 2.388,58.064 ; v1@3.683,58.217 3.531,58.064 2.388,58.064 ; v1(6.706,46.609) 6.553,46.457 2.743,46.457 2.388,46.812 2.388,58.064 ; 11.354,45.364 11.354,45.441 ; 11.76,39.319 11.76,38.176 12.421,37.516 ; 11.989,35.255 20.269,35.255 24.663,39.649 ; 12.116,37.516 14.326,35.306 ; 12.421,45.364 12.421,37.516 ; 13.081,35.306 12.421,35.966 12.421,37.516 ; 28.499,39.649 24.663,39.649 ; v1(40.234,41.402) 40.259,41.377 40.259,39.649 ; v1(63.246,41.326) 61.468,41.326 59.792,39.649 40.259,39.649 ; 24.663,39.649 40.259,39.649
  Bottom Layer w1.27: v1(1.676,70.028) 2.108,70.46 ; 2.032,70.46 2.108,70.46 ; 2.718,70.46 2.108,70.46 ; v1(6.706,46.609) 6.706,45.415 6.756,45.364 11.354,45.364 12.09,45.364 ; 12.421,45.364 12.09,45.364 ; v1(13.081,51.435) 13.081,46.355 12.09,45.364 ; v1(17.755,105.232) v1@17.755,105.385 ; P4_U1.15@71.171,128.047 71.996,128.872 P4_U1.30@71.996,129.952 ; 78.486,61.671 78.74,61.925 94.564,61.925 96.418,63.779 96.418,89.738 95.098,91.059 ; v1(81.89,41.224) 83.642,41.224 88.494,46.076 99.635,46.076 103.276,49.717 103.276,90.754 97.815,96.215 97.815,102.87 ; v5(92.913,110.16) 92.431,109.677 92.431,104.673 ; v5(95.948,112.751) 99.924,112.751 ; 97.866,112.751 99.924,110.693 ; v5(103.327,116.535) 103.327,112.776 ; v1(106.553,111.252) 106.553,112.039 105.842,112.751 103.353,112.751 ; 2.108,70.46 v1(5.309,70.46) 5.588,70.739 5.588,93.218 v1@17.755,105.385 ; v1@17.755,105.385 18.466,106.096 18.466,115.722 24.892,122.149 ; v1@17.755,105.385 17.755,116.764 23.139,122.149 24.892,122.149 ; 24.892,122.149 31.471,122.149 ; 31.471,122.149 57.226,122.149 ; 31.471,122.149 32.715,123.393 57.15,123.393 59.131,125.374 59.334,125.374 ; 57.226,122.149 57.582,122.149 ; 57.226,122.149 58.776,123.698 58.776,124.816 59.334,125.374 ; 57.582,122.149 58.877,122.149 61.544,124.816 v3(61.544,125.374) 60.808,125.374 ; 57.582,122.149 60.808,125.374 ; 59.334,125.374 60.808,125.374 ; 92.431,104.673 92.431,93.726 95.098,91.059 ; 92.431,104.673 91.288,103.53 91.288,93.218 93.447,91.059 95.098,91.059 ; 97.815,102.87 97.815,104.267 ; 97.815,102.87 99.212,104.267 ; 97.815,104.267 99.212,104.267 ; 97.815,104.267 99.924,106.375 99.924,110.693 ; 99.212,104.267 101.194,106.248 101.194,110.693 ; 99.924,110.693 99.924,112.751 ; 99.924,110.693 101.194,110.693 ; 99.924,112.751 101.194,112.751 ; 101.194,110.693 101.194,112.751 ; 101.194,110.693 101.244,110.693 103.302,112.751 ; 101.194,112.751 103.302,112.751 ; 103.302,112.751 103.353,112.751 ; 103.302,112.751 103.327,112.776 ; 103.327,112.776 103.353,112.751
AGND_U2: C1_U2.2 C2_U2.2 C3_U2.2 C4_U2.2 C12_U2.2 C14_U2.2 C33_U2.2 C46_U2.2 C53_U2.2 C55_U2.2 C56_U2.2 C57_U2.2 C58_U2.1 C59_U2.1 C60_U2.1 C62_U2.2 C63_U2.2 C64_U2.2 C65_U2.2 P4_U2.15 P4_U2.30 R9_U2.1 R10_U2.1 R11_U2.2 R12_U2.2 R14_U2.1 R71_U2.1 R72_U2.2 U1_U2.11 U2_U2.1 U4_U2.4 U5_U2.5 U7_U2.5 U8_U2.4 U10_U2.5 U12_U2.5 U13_U2.4 U14_U2.5 | length 784.1
  Top Layer w0.762: 162.865,118.821 162.979,118.935 162.979,119.926 ; v1@163.246,119.659 162.979,119.926 ; C33_U2.2@164.135,124.689 163.551,124.104 163.551,123.698 162.979,123.126 162.979,119.926 ; U5_U2.5@170.891,56.617 172.009,56.617 v1(172.034,56.642) ; v1@172.745,121.945 172.745,122.733 173.152,123.139 C63_U2.2@173.152,124.587 174.549,124.587 175.666,125.705 v5(175.666,127.33) ; U7_U2.5@196.901,40.284 v1(198.984,40.284) 200.101,41.402 C55_U2.2@200.939,41.402 202.311,42.774 C58_U2.1@203.276,42.774 ; C65_U2.2@197.942,125.07 v5@200.228,125.07 ; v5(200.304,125.679) 200.304,125.146 v5@200.228,125.07 ; C62_U2.2@200.355,124.028 200.355,124.943 v5@200.228,125.07 ; U10_U2.5@221.615,40.208 223.266,40.208 224.536,41.478 v1(225.628,41.478) ; U12_U2.5@238.912,40.208 v1@241.351,40.208 ; v1(241.351,40.31) 242.951,40.31 C56_U2.2@243.027,40.386 243.586,40.945 C60_U2.1@245.339,40.945 ; C57_U2.2@245.643,107.696 245.643,108.204 245.974,108.534 250.19,108.534 ; v1(250.952,108.534) 250.19,108.534 ; v1(251.104,94.92) 251.663,94.92 R72_U2.2@251.689,94.945 ; C64_U2.2@252.679,106.807 252.476,107.01 C59_U2.1@250.52,107.01 250.546,107.036 250.546,108.179 250.19,108.534 ; U13_U2.4@252.755,103.759 U13_U2.4@252.755,103.962 v1(252.755,105.639) C64_U2.2@252.755,106.756 ; v1(255.549,87.808) U14_U2.5@255.549,89.205
  Top Layer w1.016: R11_U2.2@138.709,100.432 138.709,102.514 R10_U2.1@138.735,102.54 ; v1(145.009,110.973) U1_U2.11@146.431,110.973 ; U4_U2.4@160.147,118.821 162.865,118.821 ; 162.979,118.935 v1(163.474,119.431) v1@163.246,119.659 ; C33_U2.2@164.135,124.689 C33_U2.2@164.313,124.689 ; v1@171.094,116.815 C14_U2.2@171.094,117.856 ; R14_U2.1@171.247,122.453 172.237,122.453 v1@172.745,121.945 ; C46_U2.2@176.759,119.177 176.835,119.101 U8_U2.4@178.918,119.101 v1(180.124,119.101) ; v1(182.88,119.075) 182.88,119.05 182.956,118.974 C53_U2.2@182.956,116.992 ; 188.163,126.848 188.001,127.01 P4_U2.30@188.001,128.047 188.001,129 P4_U2.15@188.953,129.952
  Top Layer w1.27: C1_U2.2@131.013,113.792 131.013,116.891 132.41,118.288 v3(134.645,118.288) 137.668,118.288 ; C3_U2.2@134.391,101.473 134.391,102.413 ; 134.595,106.02 134.391,105.816 134.391,102.413 ; R12_U2.2@137.719,116.561 137.719,118.237 137.668,118.288 ; R10_U2.1@138.709,102.514 138.608,102.413 134.391,102.413 ; 139.852,118.288 137.668,118.288 ; C12_U2.2@140.208,119.329 140.208,117.17 R9_U2.1@140.259,117.119 ; v5(164.109,127.203) 164.135,127.178 C33_U2.2@164.135,124.689
  Mid-Layer 1 w1.016: 188.036,126.771 188.001,126.807 P4_U2.30@188.001,128.047 188.001,129 P4_U2.15@188.953,129.952 188.953,131.468 188.925,131.496
  Bottom Layer w0.762: v1(172.034,56.642) 174.574,56.642 ; 174.879,47.498 174.879,46.787 ; 175.158,47.219 175.158,55.093 174.879,55.372 ; 175.666,58.09 174.879,57.302 174.879,56.896 ; 175.946,58.915 174.574,57.544 174.574,56.642 ; 240.868,39.827 240.386,40.31 ; 241.808,39.827 241.808,39.853 v1(241.351,40.31) ; 245.593,39.827 255.575,49.809 255.575,60.782 256.591,61.798 256.591,69.901 256.591,70.485 256.159,70.917 ; 174.574,56.642 174.574,47.092 174.879,46.787 ; 174.879,46.787 180.721,40.945 ; 174.879,55.372 174.879,56.642 ; 174.879,55.372 175.692,56.185 ; 174.879,56.642 174.879,56.896 ; 174.879,56.642 175.692,56.642 ; 174.879,56.896 175.692,57.709 175.692,56.642 ; 175.692,56.185 175.692,46.685 175.946,46.431 181.407,40.97 ; 175.692,56.185 175.692,56.642 ; 180.721,40.945 181.381,40.284 181.432,40.284 ; 180.721,40.945 181.432,40.945 ; 181.407,40.97 181.432,40.945 ; 181.407,40.97 193.142,40.97 ; 181.432,40.284 182.093,40.284 ; 181.432,40.284 181.432,40.945 ; 181.432,40.284 181.432,40.259 182.169,39.522 198.222,39.522 v1(198.984,40.284) ; 181.432,40.945 193.116,40.945 193.142,40.97 ; 181.432,40.945 182.093,40.284 ; 182.093,40.284 v1(198.984,40.284) ; 193.142,40.97 198.882,40.97 198.984,40.869 v1(198.984,40.284) ; 240.386,40.31 240.335,40.361 241.3,40.361 v1(241.351,40.31) ; 240.386,40.31 v1(241.351,40.31) ; 240.386,40.31 238.531,40.31 238.049,40.792 230.937,40.792 226.314,40.792 v1(225.628,41.478) 238.176,41.478 238.836,40.818 240.843,40.818 241.275,40.386 244.881,40.386 ; 244.881,40.386 245.466,40.386 ; 244.881,40.386 244.881,40.411 245.466,40.996 ; 244.881,40.386 244.881,39.827 245.364,39.827 245.466,39.929 245.466,40.386 ; 245.466,40.386 245.466,40.996 ; 245.466,40.386 255.041,49.962 255.041,61.138 ; 245.466,40.996 254.635,50.165 254.635,60.731 255.041,61.138 ; 255.041,61.138 256.159,62.255 256.159,70.917 ; 255.549,75.006 255.549,71.526 256.159,70.917 ; 255.549,75.006 256.159,74.397 ; 255.549,75.006 v1(255.549,87.808) 256.159,87.198 256.159,74.397 ; 256.159,70.917 256.159,74.397
  Bottom Layer w1.016: 175.666,58.09 175.806,58.229 175.806,56.756 175.692,56.642 ; 175.946,46.431 175.946,58.915 175.946,69.571 168.86,76.657 166.929,76.657 165.125,78.461 165.125,115.976 167.869,118.72 171.882,118.72 172.263,119.101 v1(180.124,119.101) 182.855,119.101 v1(182.88,119.075) ; P4_U2.30@187.909,127.955 187.909,126.289 188.468,125.73 203.454,125.73 ; P4_U2.30@187.909,127.955 187.874,127.92 187.232,127.92 187.452,128.14 187.452,129.794 188.062,130.404 188.501,130.404 P4_U2.15@188.953,129.952 188.953,129.644 188.001,128.692 P4_U2.30@188.001,128.047 P4_U2.30@187.909,127.955 ; 203.454,125.73 204.8,125.73 ; 203.454,125.73 206.273,122.911 225.374,122.911 ; 204.8,125.73 206.172,125.73 207.137,124.765 214.401,124.765 214.427,124.79 224.892,124.79 225.831,123.85 ; 204.8,125.73 206.68,123.85 225.831,123.85 ; 225.374,122.911 235.966,112.319 ; 225.374,122.911 226.771,122.911 ; 225.831,123.85 226.771,122.911 ; 226.771,122.911 235.966,113.716 235.966,113.284 ; 235.966,112.319 235.966,113.284 ; 235.966,112.319 237.515,110.769 ; 235.966,113.284 238.481,110.769 ; 237.515,110.769 238.481,110.769 ; 237.515,110.769 238.176,110.109 246.786,110.109 ; 238.481,110.769 247.244,110.769 ; 246.786,110.109 247.904,110.109 ; 246.786,110.109 251.257,105.639 v1@252.374,105.639 ; 247.244,110.769 248.615,110.769 249.276,110.109 ; 247.244,110.769 247.904,110.109 ; 247.904,110.109 249.276,110.109 ; 247.904,110.109 v1@252.374,105.639 ; 249.276,110.109 252.755,106.629 v1(252.755,105.639) v1@252.374,105.639
  Bottom Layer w1.27: v3(136.347,102.464) 132.944,102.464 130.099,105.308 130.099,113.563 131.039,114.503 133.985,114.503 134.696,115.214 134.696,119.05 137.185,119.05 145.339,127.203 v5(164.109,127.203) ; 230.937,40.792 231.902,39.827 240.868,39.827 241.808,39.827 244.881,39.827 ; 245.364,39.827 245.593,39.827 247.015,39.827 256.515,49.327 256.515,60.579 257.404,61.468 257.404,69.088 256.591,69.901
  other v1: 171.12,116.713 172.796,119.151 172.771,121.971
EN_HVWRK_U1: D13_U1.1 Q1_U1.1 R15_U1.2 R40_U1.2 | length 18.6
  Top Layer w0.762: R15_U1.2@90.805,59.004 90.805,58.826 91.592,58.039 96.088,58.039 ; Q1_U1.1@96.012,53.518 96.012,57.963 96.088,58.039 ; D13_U1.1@99.593,59.766 101.702,59.766 R40_U1.2@101.879,59.944 ; 100.686,59.944 99.492,59.944 99.492,59.106 98.425,58.039 96.088,58.039
EN_HVWRK_U2: D13_U2.1 Q1_U2.1 R15_U2.2 R40_U2.2 | length 22.6
  Top Layer w0.508: Q1_U2.1@152.603,70.256 153.035,70.688 153.035,73.228 154.381,74.574 R15_U2.2@167.742,74.574 ; R15_U2.2@167.742,74.143 D13_U2.1@167.742,76.251 ; D13_U2.1@167.792,76.378 R40_U2.2@167.792,78.461
EN_WRK_U1: P4_U1.6 R38_U1.1 R55_U1.2 | length 88.5
  Top Layer w0.381: P4_U1.6@53.899,128.047 53.899,116.433 54.483,115.849 62.738,115.849 64.287,114.3 82.474,114.3 R55_U1.2@84.15,112.624 ; R55_U1.2@83.922,112.395 R55_U1.2@84.15,112.624 ; R38_U1.1@103.911,91.135 106.553,91.135 v1(106.604,91.186) ; v1@105.639,104.546 99.746,104.546 98.692,105.6 95.842,105.6 95.83,105.588 93.426,105.588 93.413,105.6 92.413,105.6 92.401,105.588 92.126,105.588 89.51,108.204 89.51,111.963 88.646,112.827 84.353,112.827 R55_U1.2@84.15,112.624
  Bottom Layer w0.381: v1(105.664,104.572) 105.664,104.496 107.798,102.362 107.798,92.38 v1(106.604,91.186)
EN_WRK_U2: P4_U2.6 R38_U2.1 R55_U2.2 | length 71.2
  Top Layer w0.381: v1(178.765,113.868) 179.019,114.122 204.495,114.122 206.098,115.725 P4_U2.6@206.098,129.952 ; v1(215.798,116.154) 216.56,116.154 217.881,117.475 R55_U2.2@217.881,117.653
  Top Layer w0.762: v1@175.133,100.152 175.158,100.127 R38_U2.1@175.158,98.933
  Bottom Layer w0.381: v1(206.07,115.697) 206.553,116.18 v1@215.468,116.18
  Bottom Layer w0.762: v1(175.158,100.152) 175.158,110.134 178.765,113.741 v1(178.765,113.868)
ENWRK_U1: Q6_U1.3 R51_U1.1 U6_U1.13 U9_U1.13 U11_U1.13 | length 76.7
  Top Layer w0.508: v1@83.773,103.908 84.539,104.673 85.369,104.673 86.335,105.639 87.046,105.639
  Top Layer w0.762: 87.046,105.639 87.046,105.969 87.96,106.883 87.96,110.49 Q6_U1.3@88.24,110.769
  Top Layer w1.016: U6_U1.13@30.582,108.592 30.607,108.567 v1(30.607,103.784) ; v1@51.562,104.082 U9_U1.13@51.562,108.585 ; U11_U1.13@71.298,108.618 71.298,104.115 v1@71.323,104.089
  Bottom Layer w0.762: v1@71.323,104.013 v1@83.668,104.013
  Bottom Layer w1.016: v1(30.607,103.784) 30.886,104.064 71.272,104.064 v1@71.323,104.013
  other v1: 83.718,103.962 51.587,104.089 71.298,104.089
ENWRK_U2: Q6_U2.3 R51_U2.1 U6_U2.13 U9_U2.13 U11_U2.13 | length 59.9
  Top Layer w0.508: U6_U2.13@191.465,106.967 191.465,103.759 v1(191.516,103.708)
  Top Layer w0.762: v1@211.074,104.902 U9_U2.13@211.074,106.451 ; Q6_U2.3@221.742,113.487 v1(222.656,113.487) 223.723,113.487 R51_U2.1@223.749,113.462 ; v1(223.977,107.925) 224.968,107.925 226.416,106.477 v1(226.416,104.877) ; v1(231.318,105.308) U11_U2.13@231.318,107.145
  Bottom Layer w0.762: v1(191.516,103.708) 203.251,103.708 204.419,104.877 v1(226.416,104.877) 230.886,104.877 v1(231.318,105.308) ; v1(222.656,113.487) 222.656,109.245 v1(223.977,107.925)
  other v1: 211.099,104.902
FAULT_U1: P4_U1.21 U16_U1.6 | length 12
  Top Layer w0.381: P4_U1.21@54.851,129.952 54.852,120.434 55.702,119.583 U16_U1.6@56.972,119.583
FAULT_U2: P4_U2.21 U16_U2.6 | length 10
  Top Layer w0.381: U16_U2.6@203.962,119.05 204.908,119.05 205.136,119.278 205.146,119.278 P4_U2.21@205.146,128.047
GND_HVISO_U1: C38_U1.2 C39_U1.2 C40_U1.2 P3_U1.3 R18_U1.2 R34_U1.2 R46_U1.1 U17_U1.5 | length 37.6
  Top Layer w0.762: R18_U1.2@90.805,61.392 91.389,61.392 92.964,59.817 R34_U1.2@93.726,59.817 ; R34_U1.2@93.751,59.792 R34_U1.2@93.726,59.817 ; R34_U1.2@94.082,59.792 96.317,59.792 ; 95.479,59.919 95.402,59.842 ; R46_U1.1@97.282,59.868 97.257,59.842 95.402,59.842 ; C38_U1.2@101.117,66.904 101.117,65.557 100.533,64.973 97.307,64.973 95.555,63.221 95.555,60.274 95.123,59.842 95.402,59.842 ; R34_U1.2@93.726,59.817 95.377,59.817 95.402,59.842
  Top Layer w1.27: P3_U1.3@93.294,77.8 93.294,76.86 95.072,75.082 U17_U1.5@98.831,75.082 98.831,73.838 101.117,71.552 C38_U1.2@101.117,66.904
